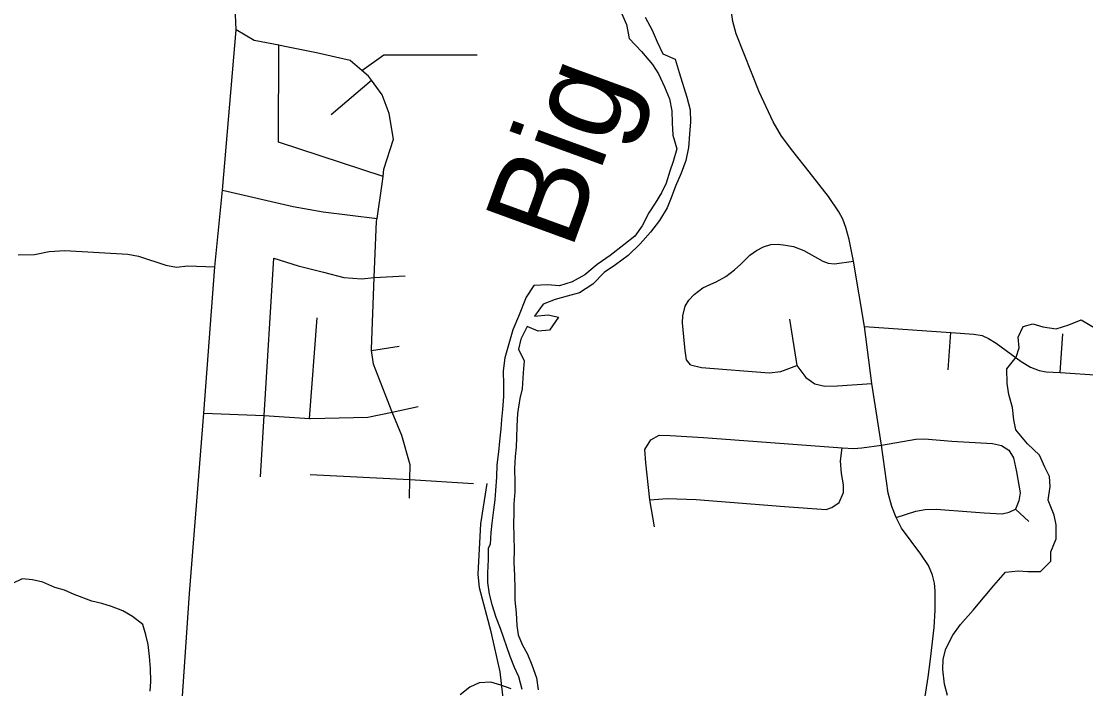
# Model space of a CAD drawing. Extents: x 208586767.6 to 208586821.4, y -134301046.9 to -134301022.9.
# Drawn here: x 208586779.165 to 208586780.239, y -134301028.455 to -134301027.783 of the extents above; entities that cross this region are included whole.
import ezdxf

# ---------------------------------------------------------------- set-up
doc = ezdxf.new("R2010")
doc.units = 0
for name, color, linetype in [('GM_X_City_Street', 7, 'Continuous'), ('GM_X_County_Road', 7, 'Continuous'), ('GM_X_Major_River', 7, 'Continuous'), ('GM_X_Major_River_Text', 7, 'Continuous'), ('GM_X_Minor_River', 7, 'Continuous')]:
    doc.layers.add(name, color=color, linetype=linetype)

msp = doc.modelspace()

# ---------------------------------------------------------------- linework, layer by layer
at = {"layer": 'GM_X_City_Street'}
for p, q in [((208586779.4778, -134301027.8769), (208586779.5185, -134301027.8425)), ((208586779.5212, -134301028.0411), (208586779.5525, -134301028.0394)), ((208586779.456, -134301028.1831), (208586779.4637, -134301028.0818)), ((208586780.0998, -134301028.1342), (208586780.1024, -134301028.0965)), ((208586780.2128, -134301028.1367), (208586780.2154, -134301028.0978)), ((208586779.5185, -134301028.1147), (208586779.5463, -134301028.1104)), ((208586779.4066, -134301028.2418), (208586779.4102, -134301028.1802)), ((208586779.4566, -134301028.2394), (208586779.557, -134301028.2447)), ((208586779.557, -134301028.2447), (208586779.6214, -134301028.2487)), ((208586780.1677, -134301028.2743), (208586780.1811, -134301028.287))]:
    msp.add_line(p, q, dxfattribs=at)
for points in [[(208586779.3176, -134301028.6151), (208586779.335, -134301028.3594), (208586779.3492, -134301028.1779), (208586779.3605, -134301028.0303), (208586779.3683, -134301027.9533), (208586779.382, -134301027.7917), (208586779.381, -134301027.7687), (208586779.3773, -134301027.7557), (208586779.3719, -134301027.7441), (208586779.3636, -134301027.7303), (208586779.3534, -134301027.7198), (208586779.3321, -134301027.7002), (208586779.3245, -134301027.691), (208586779.3157, -134301027.679), (208586779.3096, -134301027.6689)], [(208586779.5567, -134301028.2633), (208586779.557, -134301028.2447), (208586779.5573, -134301028.2299), (208586779.5489, -134301028.2003), (208586779.5391, -134301028.1767), (208586779.5206, -134301028.1283), (208586779.5185, -134301028.1147), (208586779.5183, -134301028.1132), (208586779.5212, -134301028.0411), (208586779.5236, -134301027.9845), (208586779.524, -134301027.9817), (208586779.5291, -134301027.9469), (208586779.5301, -134301027.9393), (208586779.531, -134301027.9321), (208586779.5407, -134301027.9017), (208586779.5364, -134301027.8759), (208586779.5292, -134301027.857), (208586779.5185, -134301027.8425), (208586779.5155, -134301027.8384), (208586779.5087, -134301027.8327), (208586779.4969, -134301027.8226), (208586779.4628, -134301027.8147), (208586779.4294, -134301027.808), (208586779.4249, -134301027.8071), (208586779.4002, -134301027.8024), (208586779.382, -134301027.7917)], [(208586779.5301, -134301027.9393), (208586779.4248, -134301027.9048), (208586779.4249, -134301027.8071)], [(208586779.5087, -134301027.8327), (208586779.5309, -134301027.8168), (208586779.6249, -134301027.8168)], [(208586779.3683, -134301027.9533), (208586779.4394, -134301027.9696), (208586779.4697, -134301027.9748), (208586779.524, -134301027.9817)], [(208586779.8384, -134301028.0638), (208586779.8438, -134301028.0582), (208586779.8526, -134301028.0514), (208586779.8604, -134301028.0477), (208586779.8659, -134301028.0456), (208586779.8757, -134301028.0402), (208586779.8845, -134301028.0334), (208586779.8908, -134301028.0278), (208586779.8999, -134301028.0187), (208586779.9065, -134301028.0139), (208586779.9138, -134301028.0103), (208586779.921, -134301028.008), (208586779.9286, -134301028.0075), (208586779.9357, -134301028.0084), (208586779.944, -134301028.01), (208586779.9544, -134301028.014), (208586779.965, -134301028.0198), (208586779.9735, -134301028.0246), (208586779.979, -134301028.0266), (208586779.9851, -134301028.0273), (208586780.0044, -134301028.0245)], [(208586779.162, -134301028.0183), (208586779.1787, -134301028.0179), (208586779.1934, -134301028.0148), (208586779.2093, -134301028.014), (208586779.2726, -134301028.0176), (208586779.2836, -134301028.0195), (208586779.3112, -134301028.0288), (208586779.3219, -134301028.0307), (208586779.3328, -134301028.0295), (208586779.3605, -134301028.0303)], [(208586779.4102, -134301028.1802), (208586779.4199, -134301028.0217), (208586779.4446, -134301028.0295), (208586779.4699, -134301028.0359), (208586779.4904, -134301028.0412), (208586779.5086, -134301028.0426), (208586779.5212, -134301028.0411)], [(208586779.8401, -134301028.129), (208586779.8362, -134301028.1239), (208586779.8346, -134301028.1145), (208586779.8335, -134301028.1008), (208586779.832, -134301028.0869), (208586779.8325, -134301028.0796), (208586779.8347, -134301028.0701), (208586779.8384, -134301028.0638)], [(208586779.9399, -134301028.083), (208586779.9474, -134301028.1298), (208586779.9564, -134301028.142), (208586779.9654, -134301028.1483), (208586779.9756, -134301028.1506), (208586779.9882, -134301028.1502), (208586780.023, -134301028.148)], [(208586780.0155, -134301028.0905), (208586780.1024, -134301028.0965), (208586780.1259, -134301028.0982), (208586780.1341, -134301028.0996), (208586780.1406, -134301028.1026), (208586780.1484, -134301028.1071), (208586780.1734, -134301028.1257), (208586780.183, -134301028.1314), (208586780.1917, -134301028.1349), (208586780.1988, -134301028.1361), (208586780.2128, -134301028.1367), (208586780.2928, -134301028.1423), (208586780.3547, -134301028.147), (208586780.3744, -134301028.1461)], [(208586779.8401, -134301028.129), (208586779.8511, -134301028.1318), (208586779.9195, -134301028.1373), (208586779.9312, -134301028.1357), (208586779.9474, -134301028.1298)], [(208586779.3492, -134301028.1779), (208586779.4102, -134301028.1802), (208586779.456, -134301028.1831), (208586779.4568, -134301028.1832), (208586779.5147, -134301028.1819), (208586779.5391, -134301028.1767), (208586779.5655, -134301028.1711)], [(208586779.8038, -134301028.2921), (208586779.7991, -134301028.2652), (208586779.795, -134301028.2277), (208586779.794, -134301028.2142), (208586779.8001, -134301028.2045)], [(208586779.8001, -134301028.2045), (208586779.8084, -134301028.1999), (208586779.8195, -134301028.2003), (208586779.8531, -134301028.2024), (208586779.9931, -134301028.2126), (208586780.0047, -134301028.2133), (208586780.0128, -134301028.2126), (208586780.0325, -134301028.21)], [(208586780.0325, -134301028.21), (208586780.0673, -134301028.2038), (208586780.0759, -134301028.2036), (208586780.1037, -134301028.2061), (208586780.1447, -134301028.2084), (208586780.1535, -134301028.2105), (208586780.161, -134301028.2149), (208586780.1658, -134301028.2228), (208586780.1688, -134301028.2367), (208586780.1723, -134301028.258), (208586780.1711, -134301028.2661), (208586780.1677, -134301028.2743)], [(208586779.7991, -134301028.2652), (208586779.8167, -134301028.2638), (208586779.8457, -134301028.2648), (208586779.9347, -134301028.2719), (208586779.9769, -134301028.2747), (208586779.9827, -134301028.2729), (208586779.9899, -134301028.2678), (208586779.9945, -134301028.2576), (208586779.9945, -134301028.2501), (208586779.9922, -134301028.2386), (208586779.9913, -134301028.2258), (208586779.9931, -134301028.2126)], [(208586779.6538, -134301028.4885), (208586779.6482, -134301028.4383), (208586779.6391, -134301028.3979), (208586779.6273, -134301028.3537), (208586779.6261, -134301028.34), (208586779.6288, -134301028.2892), (208586779.6349, -134301028.2487)], [(208586780.0474, -134301028.2828), (208586780.0671, -134301028.2766), (208586780.0768, -134301028.2747), (208586780.0879, -134301028.2745), (208586780.1229, -134301028.2773), (208586780.1361, -134301028.2782), (208586780.1542, -134301028.2791), (208586780.1614, -134301028.2775), (208586780.1677, -134301028.2743)]]:
    msp.add_lwpolyline(points, dxfattribs=at)
at = {"layer": 'GM_X_County_Road'}
msp.add_lwpolyline([(208586780.0755, -134301028.4696), (208586780.0798, -134301028.4436), (208586780.0819, -134301028.4254), (208586780.0856, -134301028.3938), (208586780.0866, -134301028.3761), (208586780.0869, -134301028.3627), (208586780.0868, -134301028.3566), (208586780.0861, -134301028.3491), (208586780.0842, -134301028.3408), (208586780.0801, -134301028.3313), (208586780.0722, -134301028.3199), (208586780.0529, -134301028.2937), (208586780.0474, -134301028.2828), (208586780.043, -134301028.2719), (208586780.0395, -134301028.2585), (208586780.0325, -134301028.21), (208586780.023, -134301028.148), (208586780.0155, -134301028.0905), (208586780.0044, -134301028.0245), (208586780.0002, -134301028.0029), (208586779.9968, -134301027.9907), (208586779.9935, -134301027.9822), (208586779.9895, -134301027.9749), (208586779.9792, -134301027.9594), (208586779.9597, -134301027.9347), (208586779.9433, -134301027.914), (208586779.9317, -134301027.8988), (208586779.9235, -134301027.8842), (208586779.9092, -134301027.8541), (208586779.8861, -134301027.7958), (208586779.8829, -134301027.7833), (208586779.881, -134301027.7715)], dxfattribs=at)
at = {"layer": 'GM_X_Major_River'}
for points in [[(208586779.7696, -134301027.7724), (208586779.7756, -134301027.7864), (208586779.7782, -134301027.8005), (208586779.7906, -134301027.8135), (208586779.8019, -134301027.8264), (208586779.8079, -134301027.8359), (208586779.814, -134301027.8489), (208586779.8188, -134301027.861), (208586779.8214, -134301027.8732), (208586779.8217, -134301027.8854), (208586779.8221, -134301027.8979), (208586779.8262, -134301027.9116), (208586779.8227, -134301027.9241), (208586779.8192, -134301027.9339), (208586779.8154, -134301027.9461), (208586779.8108, -134301027.9559), (208586779.8046, -134301027.9661), (208586779.7982, -134301027.976), (208586779.7913, -134301027.9889), (208586779.784, -134301027.9995), (208586779.773, -134301028.0081), (208586779.7589, -134301028.0191), (208586779.7459, -134301028.0281), (208586779.7334, -134301028.0383), (208586779.7208, -134301028.0455), (208586779.7079, -134301028.0496), (208586779.6958, -134301028.0484), (208586779.6821, -134301028.0491), (208586779.6745, -134301028.0608), (208586779.6668, -134301028.0805), (208586779.661, -134301028.0938), (208586779.6568, -134301028.1078), (208586779.6529, -134301028.1219), (208586779.6513, -134301028.1351), (208586779.6516, -134301028.1492), (208586779.6516, -134301028.161), (208586779.6504, -134301028.1742), (208586779.6496, -134301028.1841), (208586779.6488, -134301028.1936), (208586779.6476, -134301028.2061), (208586779.6464, -134301028.2167), (208586779.6448, -134301028.2297), (208586779.6444, -134301028.2422), (208586779.6435, -134301028.2555), (208586779.6427, -134301028.2649), (208586779.6415, -134301028.2752), (208586779.6396, -134301028.2885), (208586779.6388, -134301028.298), (208586779.638, -134301028.3101)], [(208586779.7942, -134301027.7789), (208586779.8013, -134301027.7919), (208586779.8066, -134301027.8037), (208586779.8122, -134301027.8158), (208586779.8247, -134301027.8212), (208586779.8288, -134301027.8345), (208586779.8363, -134301027.8596), (208586779.8396, -134301027.8721), (208586779.84, -134301027.8843), (208586779.8391, -134301027.8968), (208586779.8379, -134301027.9101), (208586779.8352, -134301027.9234), (208586779.8306, -134301027.9359), (208586779.8248, -134301027.9492), (208586779.8206, -134301027.9609), (208586779.8164, -134301027.9711), (208586779.8087, -134301027.9836), (208586779.7996, -134301027.9954), (208586779.7893, -134301028.0071), (208586779.7771, -134301028.0188), (208586779.7645, -134301028.0282), (208586779.7531, -134301028.0361), (208586779.7417, -134301028.0479), (208586779.7283, -134301028.0565), (208586779.7158, -134301028.0599), (208586779.7037, -134301028.0633), (208586779.6915, -134301028.0681), (208586779.6827, -134301028.0799), (208586779.6964, -134301028.0788), (208586779.707, -134301028.0811), (208586779.6978, -134301028.094), (208586779.6864, -134301028.0951), (208586779.6755, -134301028.0905), (208586779.6689, -134301028.1033), (208586779.6666, -134301028.1132), (208586779.6722, -134301028.125), (208586779.6714, -134301028.1371), (208586779.6702, -134301028.1531), (208586779.6679, -134301028.1629), (208586779.6655, -134301028.1781), (208586779.6651, -134301028.191), (208586779.6647, -134301028.2024), (208586779.6642, -134301028.2119), (208586779.6634, -134301028.2214), (208586779.6626, -134301028.2335), (208586779.6629, -134301028.2476), (208586779.6629, -134301028.2571), (208586779.6621, -134301028.2692), (208586779.662, -134301028.2787), (208586779.6616, -134301028.2886), (208586779.6619, -134301028.3026), (208586779.6622, -134301028.3148), (208586779.6618, -134301028.3277), (208586779.6625, -134301028.3417), (208586779.6628, -134301028.3543), (208586779.6631, -134301028.366), (208586779.6642, -134301028.3789), (208586779.6649, -134301028.3915), (208586779.6663, -134301028.401), (208586779.6705, -134301028.4109), (208586779.6757, -134301028.4204), (208586779.6802, -134301028.4314), (208586779.6847, -134301028.4443), (208586779.6865, -134301028.4565)], [(208586779.638, -134301028.3101), (208586779.636, -134301028.3139), (208586779.636, -134301028.3253), (208586779.6355, -134301028.3386), (208586779.6355, -134301028.3484), (208586779.637, -134301028.3602), (208586779.6396, -134301028.3705), (208586779.6437, -134301028.3834), (208586779.6482, -134301028.3944), (208586779.6579, -134301028.4226), (208586779.6624, -134301028.4336), (208586779.6665, -134301028.4431), (208586779.6699, -134301028.4557)]]:
    msp.add_lwpolyline(points, dxfattribs=at)
at = {"layer": 'GM_X_Minor_River'}
for points in [[(208586780.0992, -134301028.4621), (208586780.0963, -134301028.4507), (208586780.0945, -134301028.4359), (208586780.0949, -134301028.4257), (208586780.0976, -134301028.4151), (208586780.1045, -134301028.4014), (208586780.1122, -134301028.3905), (208586780.1252, -134301028.3761), (208586780.1371, -134301028.3618), (208586780.1458, -134301028.3512), (208586780.1577, -134301028.338), (208586780.1706, -134301028.3366), (208586780.1801, -134301028.3374), (208586780.193, -134301028.3371), (208586780.2033, -134301028.3269), (208586780.2034, -134301028.3174), (208586780.2088, -134301028.3045), (208586780.2089, -134301028.2901), (208586780.2066, -134301028.2806), (208586780.2007, -134301028.2654), (208586780.2026, -134301028.2517), (208586780.2019, -134301028.2415), (208586780.1975, -134301028.232), (208586780.1918, -134301028.2202), (208586780.1798, -134301028.2087), (208586780.1681, -134301028.1946), (208586780.1662, -134301028.1844), (208586780.1648, -134301028.1722), (208586780.1611, -134301028.1589), (208586780.1593, -134301028.1479), (208586780.159, -134301028.1331), (208586780.1685, -134301028.1214), (208586780.1713, -134301028.1119), (208586780.1706, -134301028.1013), (208586780.1756, -134301028.0903), (208586780.1851, -134301028.0877), (208586780.1953, -134301028.0908), (208586780.2089, -134301028.0928), (208586780.2215, -134301028.0887), (208586780.2341, -134301028.0838), (208586780.2488, -134301028.0926)], [(208586779.2954, -134301028.4579), (208586779.2959, -134301028.4481), (208586779.2956, -134301028.4351), (208586779.2946, -134301028.423), (208586779.2932, -134301028.4108), (208586779.291, -134301028.4009), (208586779.2877, -134301028.3906), (208586779.2775, -134301028.3826), (208586779.2677, -134301028.3768), (208586779.2564, -134301028.3725), (208586779.2466, -134301028.3694), (208586779.2364, -134301028.367), (208586779.2186, -134301028.3604), (208586779.2088, -134301028.3561), (208586779.199, -134301028.3534), (208586779.1869, -134301028.3479), (208586779.1767, -134301028.3456), (208586779.1661, -134301028.3447), (208586779.1566, -134301028.3492)], [(208586779.6593, -134301028.4556), (208586779.6487, -134301028.4517), (208586779.6389, -134301028.4486), (208586779.6271, -134301028.4493), (208586779.6176, -134301028.4537), (208586779.6077, -134301028.4616)]]:
    msp.add_lwpolyline(points, dxfattribs=at)

# ---------------------------------------------------------------- texts
at = {"layer": 'GM_X_Major_River_Text'}
msp.add_text('Big', height=0.0947, rotation=69.9999, dxfattribs=at).set_placement((208586779.7196, -134301028.0151))

doc.saveas('drawing.dxf')
